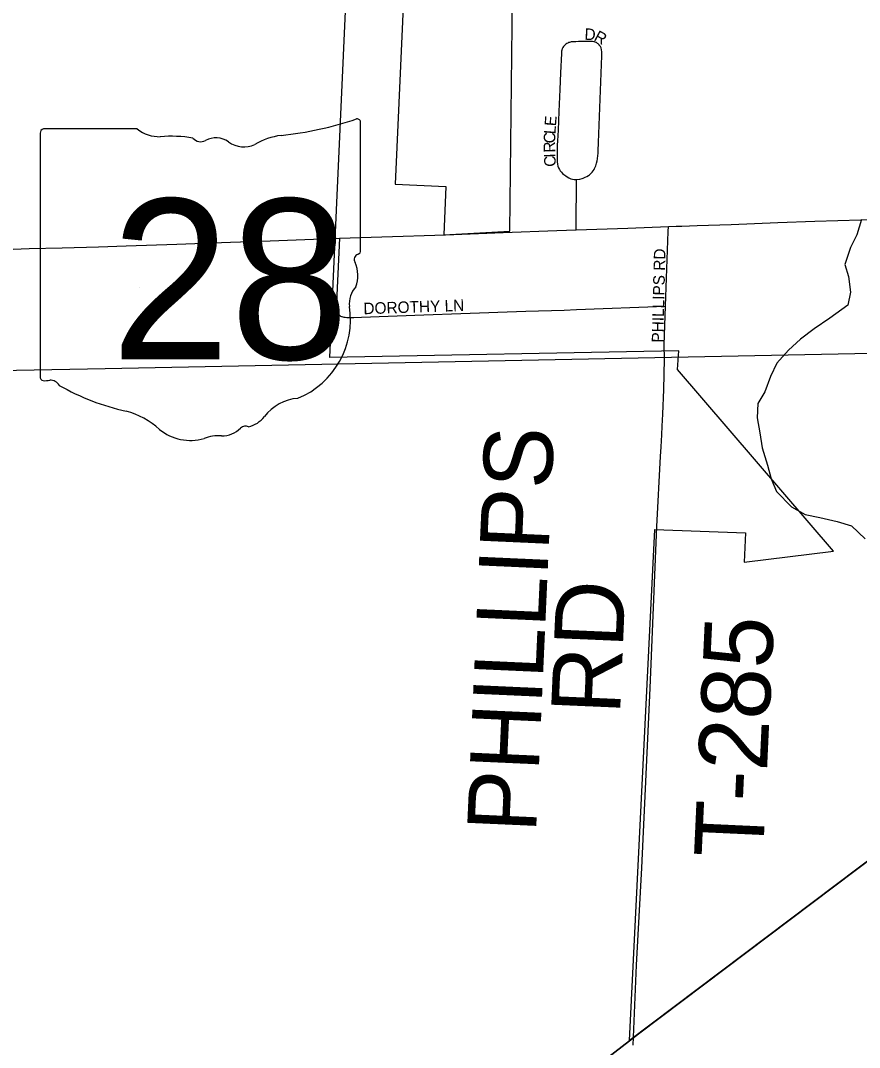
# Model space of a CAD drawing. Extents: x 1442749 to 1756758, y 235267 to 677782.
# Drawn here: x 1626273 to 1629919, y 480789 to 485248 of the extents above; entities that cross this region are included whole.
import ezdxf

# ---------------------------------------------------------------- set-up
doc = ezdxf.new("R2010")
doc.units = 0
for name, color, linetype in [('GM_X_Adjacent_County', 7, 'Continuous'), ('GM_X_City_Street', 7, 'Continuous'), ('GM_X_City_Street_Text', 7, 'Continuous'), ('GM_X_Corporation', 7, 'Continuous'), ('GM_X_County', 7, 'Continuous'), ('GM_X_Major_River', 7, 'Continuous'), ('GM_X_Rail_Line', 7, 'Continuous'), ('GM_X_State_Location', 7, 'Continuous'), ('GM_X_State_Route', 7, 'Continuous'), ('GM_X_State_Shield', 7, 'Continuous'), ('GM_X_Township', 7, 'Continuous'), ('GM_X_Township_Road', 7, 'Continuous'), ('GM_X_Township_Road_Text', 7, 'Continuous')]:
    doc.layers.add(name, color=color, linetype=linetype)

msp = doc.modelspace()

# ---------------------------------------------------------------- linework, layer by layer
at = {"layer": 'GM_X_Adjacent_County'}
msp.add_lwpolyline([(1614699.6, 470049.9), (1618603.7, 472951.5), (1620523.4, 474378.3), (1621965.9, 475450.6), (1621996.8, 475474.4), (1628918.9, 480817.5), (1628957.6, 480847.4), (1631412.7, 482696.3), (1633247.9, 484078.4), (1633505.1, 484271.9), (1633818.5, 484508), (1635644.3, 485882.8), (1638041.6, 487688), (1640676.2, 489671.7), (1647133.1, 494533.2), (1648022.8, 495203.1), (1648788, 495779.1), (1655740.7, 500852.4)], dxfattribs=at)
at = {"layer": 'GM_X_City_Street'}
for points in [[(1628687.5, 484339.3), (1628687.5, 484354.1), (1628688.2, 484557.4), (1628703.9, 484560), (1628713.6, 484562.4), (1628718.1, 484564), (1628726, 484567.5), (1628733.6, 484571.5), (1628740.3, 484575.8), (1628744.7, 484578.7), (1628749.4, 484582.3), (1628753.8, 484586.4), (1628757.3, 484590), (1628761.4, 484595.2), (1628765.2, 484600.7), (1628767.5, 484605.4), (1628770.5, 484612.1), (1628772.2, 484616.9), (1628775.6, 484628.8), (1628777.9, 484638.6), (1628779.7, 484647.4), (1628781.6, 484661.7), (1628782.5, 484671), (1628783.3, 484683), (1628785, 484718.4), (1628798.7, 485095.6), (1628798.8, 485100.9), (1628798.8, 485106.1), (1628798.7, 485111.3), (1628798.5, 485113.7), (1628797.9, 485119.1), (1628797.3, 485122.2), (1628795.9, 485127.9), (1628795.4, 485129.4), (1628794.1, 485132.5), (1628792.5, 485135.6), (1628790.7, 485138.6), (1628789.9, 485139.7), (1628788, 485141.9), (1628785.5, 485144.6), (1628783.2, 485146.6), (1628780.5, 485148.8), (1628778.5, 485150.3), (1628777.2, 485151.1), (1628775.1, 485152.4), (1628773.6, 485153.3), (1628770.5, 485154.7), (1628767.1, 485155.7), (1628764.1, 485156.2), (1628758, 485157), (1628746.3, 485157.7), (1628706.3, 485157.1), (1628698.2, 485157), (1628685.9, 485156.5), (1628677.9, 485156.1), (1628671.8, 485155.7), (1628665.8, 485155.1), (1628662.5, 485154.6), (1628658.1, 485153.6), (1628654.6, 485152.4), (1628650.7, 485150.6), (1628647.2, 485148.6), (1628642.8, 485145.4), (1628638.8, 485141.8), (1628635.3, 485138.3), (1628632.9, 485135.5), (1628629.6, 485131.1), (1628628, 485128.1), (1628626.7, 485125.4), (1628626, 485123.5), (1628625.4, 485121.3), (1628625, 485119.7), (1628624.3, 485114.8), (1628623.9, 485110.9), (1628623.5, 485105.1), (1628619.9, 485020.7), (1628616.6, 484948.8), (1628612.4, 484853.8), (1628608.8, 484772.1), (1628605.9, 484726.4), (1628605.2, 484706.9), (1628604.3, 484648.5), (1628604.9, 484635), (1628606.1, 484624.9), (1628607.8, 484616.4), (1628610.3, 484609.3), (1628614.3, 484601.4), (1628617.6, 484596.3), (1628623.1, 484589.6), (1628628.4, 484584.5), (1628634.2, 484579.5), (1628642, 484573.4), (1628648, 484569.4), (1628655.6, 484565.1), (1628664.8, 484561.5), (1628671.3, 484559.7), (1628678.9, 484558.4), (1628688.2, 484557.4)], [(1629076.1, 484007.4), (1629087.3, 484332.6), (1629088, 484353.4)], [(1627658.5, 484302.7), (1627647.9, 484055.1), (1627646, 484005.4), (1627646, 483996.2), (1627646.1, 483993.8), (1627646.6, 483989.6), (1627647, 483987.1), (1627648.1, 483983.2), (1627649.2, 483980.4), (1627651.3, 483976.5), (1627654.3, 483972.5), (1627657.7, 483969.1), (1627660.4, 483967.2), (1627663.8, 483965.1), (1627666.9, 483963.7), (1627669.7, 483962.6), (1627672.9, 483961.8), (1627678, 483960.8), (1627683.3, 483960), (1627690.7, 483959.3), (1627704.9, 483958.7), (1627721.1, 483958.6), (1627753.9, 483959.5), (1628025.4, 483969.8), (1628186.1, 483975.5), (1628468, 483986.7), (1628635.9, 483991.1), (1628689.4, 483992.8), (1629076.1, 484007.4)], [(1629070, 483839.6), (1629076.1, 484007.4)]]:
    msp.add_lwpolyline(points, dxfattribs=at)
at = {"layer": 'GM_X_Corporation'}
for points in [[(1635210.5, 485557.9), (1633823.1, 484511.4), (1633262.6, 484089.3), (1631412.7, 482696.3), (1628918.9, 480818.3), (1629029.5, 483037.3), (1629422.5, 483023.6), (1629418.1, 482896.7), (1629805, 482944.2), (1629128.1, 483732.4), (1629133.5, 483814.4), (1627617.6, 483785.3), (1627690.6, 485417.7)], [(1627940.4, 485406.5), (1627901.5, 484537.4), (1628121.3, 484527.5), (1628111.9, 484317.1), (1628398.4, 484333), (1628411.3, 485353.8)]]:
    msp.add_lwpolyline(points, dxfattribs=at)
at = {"layer": 'GM_X_County'}
msp.add_lwpolyline([(1655740.7, 500852.4), (1648788, 495779.1), (1648022.8, 495203.1), (1647133.1, 494533.2), (1640676.2, 489671.7), (1638041.6, 487688), (1635644.3, 485882.8), (1633818.5, 484508), (1633505.1, 484271.9), (1633247.9, 484078.4), (1631412.7, 482696.3), (1628957.6, 480847.4), (1628918.9, 480817.5), (1621996.8, 475474.4), (1621965.9, 475450.6), (1620523.4, 474378.3), (1618603.7, 472951.5), (1614699.6, 470049.9)], dxfattribs=at)
at = {"layer": 'GM_X_Major_River'}
msp.add_lwpolyline([(1629927.6, 484384), (1629906.7, 484318.2), (1629880, 484262.4), (1629855, 484188.6), (1629870.3, 484136.4), (1629879.4, 484068.1), (1629868.6, 484012.2), (1629789.8, 483955.1), (1629721.1, 483909.9), (1629662.5, 483864.6), (1629609.8, 483817.2), (1629559, 483759.8), (1629532.2, 483702), (1629507.3, 483636.3), (1629476.6, 483584.6), (1629473.7, 483522.5), (1629484.9, 483458.3), (1629496, 483392), (1629519, 483317.6), (1629534.2, 483257.3), (1629557.5, 483203), (1629622.7, 483136), (1629682.3, 483103.2), (1629746.2, 483090.3), (1629822, 483073.3), (1629883.8, 483054.5), (1629943.1, 482997.7)], dxfattribs=at)
at = {"layer": 'GM_X_Rail_Line'}
msp.add_lwpolyline([(1615664.4, 483549), (1619432.2, 483601), (1621936.9, 483649), (1626640.3, 483737.7), (1630912.8, 483823), (1632952.2, 483864.7)], dxfattribs=at)
at = {"layer": 'GM_X_State_Route'}
for points in [[(1629146, 484355.5), (1629213.5, 484358.1), (1629360.9, 484362), (1629563.9, 484370.7), (1629724.4, 484377.2), (1629924.4, 484383.2), (1630288.1, 484394.4), (1630391.7, 484397), (1630409.3, 484397.5), (1630494.5, 484400.3), (1630652, 484405.1), (1630740.3, 484407.8), (1630860.4, 484413.1), (1630864.7, 484413.3), (1631028, 484420.9), (1631067.8, 484422.8), (1631156.3, 484425.9)], [(1627658.5, 484302.7), (1627842.2, 484308.3), (1628119.7, 484318), (1628370.4, 484328), (1628603.9, 484336.3), (1628687.5, 484339.3), (1628912, 484347.2), (1629088, 484353.4), (1629121.7, 484354.6), (1629146, 484355.5)], [(1626099.9, 484249.7), (1626309.6, 484257.6), (1626453.9, 484261.4), (1626611.1, 484265.6), (1626732.4, 484269.8), (1626951.9, 484277.2), (1627185.4, 484286.4), (1627357.8, 484292.3), (1627658.5, 484302.7)]]:
    msp.add_lwpolyline(points, dxfattribs=at)
at = {"layer": 'GM_X_State_Shield'}
for p, q in [((1626779.9, 484777.4), (1626372.2, 484777.4)), ((1627750.7, 484250.9), (1627750.7, 484803.6)), ((1626358.5, 484759.3), (1626358.5, 483702.6)), ((1627750.5, 484251), (1627750.7, 484250.9))]:
    msp.add_line(p, q, dxfattribs=at)
for centre, radius, start, end in [((1627254.8, 486218), 1476.4, 275.8445, 288.9065), ((1627735.2, 484805.9), 15.5, 351.8621, 97.738), ((1626374.5, 484761.5), 16.1, 98.1301, 188.1301), ((1626877, 484900.1), 156.4, 231.6195, 271.1119), ((1626928.9, 484184.2), 561.6, 80.4867, 94.9883), ((1627056.4, 484767), 45.1, 219.7921, 297.1024), ((1627122.6, 484644.9), 93.8, 54.4667, 119.1411), ((1627243.7, 484812.4), 112.9, 233.8562, 294.8282), ((1627443.1, 484454.7), 297, 97.3462, 120.7689), ((1627747.1, 484210.3), 24, 107.944, 210.337), ((1627734.1, 484248.8), 16.6, 289.6038, 7.7341), ((1627594.5, 484140.4), 144, 340.033, 23.6496), ((1627806.2, 484019.6), 104.8, 136.8065, 186.9296), ((1627337.5, 483949.3), 369.3, 292.3089, 8.9858), ((1626374.6, 483700.3), 16.3, 171.9584, 258.3066), ((1626377.1, 483808.4), 124.2, 267.339, 280.6039), ((1626402.5, 483641.7), 44.8, 29.7484, 93.2717), ((1626967.7, 484591), 1066.1, 240.4129, 257.1985), ((1627493.2, 483406), 202.2, 94.4031, 142.5768), ((1626649.9, 483227.9), 333.6, 47.1842, 75.836), ((1627236.9, 483600.2), 119.3, 282.8732, 323.2771), ((1627010.7, 483636.4), 211.7, 230.7004, 286.2918), ((1627148.4, 483557.3), 112.8, 268.777, 315.5493), ((1627250.5, 483455), 31.8, 65.7517, 132.6484), ((1627133, 483271.1), 173.9, 85.6951, 111.2099)]:
    msp.add_arc(centre, radius, start, end, dxfattribs=at)
at = {"layer": 'GM_X_Township'}
msp.add_lwpolyline([(1642919, 502378.9), (1644427, 500258.8), (1647406, 496053.3), (1648022.8, 495203.1), (1647133.1, 494533.2), (1640676.2, 489671.7), (1638041.6, 487688), (1635644.3, 485882.8), (1633818.5, 484508), (1633505.1, 484271.9), (1633247.9, 484078.4), (1631412.7, 482696.3), (1628957.6, 480847.4), (1628918.9, 480817.5), (1621996.8, 475474.4), (1621965.9, 475450.6), (1620523.4, 474378.3), (1618603.7, 472951.5), (1618173.2, 474474.4), (1617334.6, 477440.8), (1616957.7, 478774.1)], dxfattribs=at)
at = {"layer": 'GM_X_Township_Road'}
for points in [[(1629070.8, 483777), (1629070, 483839.6)], [(1629037.3, 483051), (1629054.3, 483354.3), (1629056.7, 483397), (1629059.6, 483449.6), (1629061.5, 483487.2), (1629063.9, 483538.9), (1629068.3, 483646.6), (1629070.8, 483777)], [(1628935, 480798.1), (1628950.2, 481146.3), (1628972.6, 481568.5), (1629008.9, 482349.2), (1629037.3, 483051)]]:
    msp.add_lwpolyline(points, dxfattribs=at)

# ---------------------------------------------------------------- texts
at = {"layer": 'GM_X_City_Street_Text'}
for s, rotation, p in [('D', 356.4564, (1628722.3, 485165.1)), ('R', 331.4147, (1628760.7, 485163.9)), ('E', 85.7606, (1628599.6, 484788.4)), ('L', 85.8716, (1628597.1, 484753.3)), ('C', 87.984, (1628595.7, 484714.2)), ('R', 91.7732, (1628596.9, 484675.5)), ('I', 92.2173, (1628597.8, 484653.6)), ('C', 92.1858, (1628599.3, 484614)), ('PHILLIPS RD', 88.6036, (1629065.7, 483849.1)), ('DOROTHY LN', 1.9105, (1627763.6, 483972.6))]:
    msp.add_text(s, height=50, rotation=rotation, dxfattribs=at).set_placement(p)
at = {"layer": 'GM_X_State_Location'}
for s in ['s', 'r']:
    msp.add_text(s, height=1, dxfattribs=at).set_placement((1627038.9, 484160.7))
msp.add_text('28', height=1, rotation=0, dxfattribs=at).set_placement((1626787.1, 484088))
at = {"layer": 'GM_X_State_Shield'}
msp.add_text('28', height=696.1, dxfattribs=at).set_placement((1626665.4, 483777.1))
at = {"layer": 'GM_X_Township_Road_Text'}
for s, rotation, p in [('PHILLIPS', 87.4332, (1628512.6, 481717.9)), ('RD', 87.5314, (1628877.6, 482231.3)), ('T-285', 87.366, (1629499, 481607.3))]:
    msp.add_text(s, height=300, rotation=rotation, dxfattribs=at).set_placement(p)

doc.saveas('drawing.dxf')
